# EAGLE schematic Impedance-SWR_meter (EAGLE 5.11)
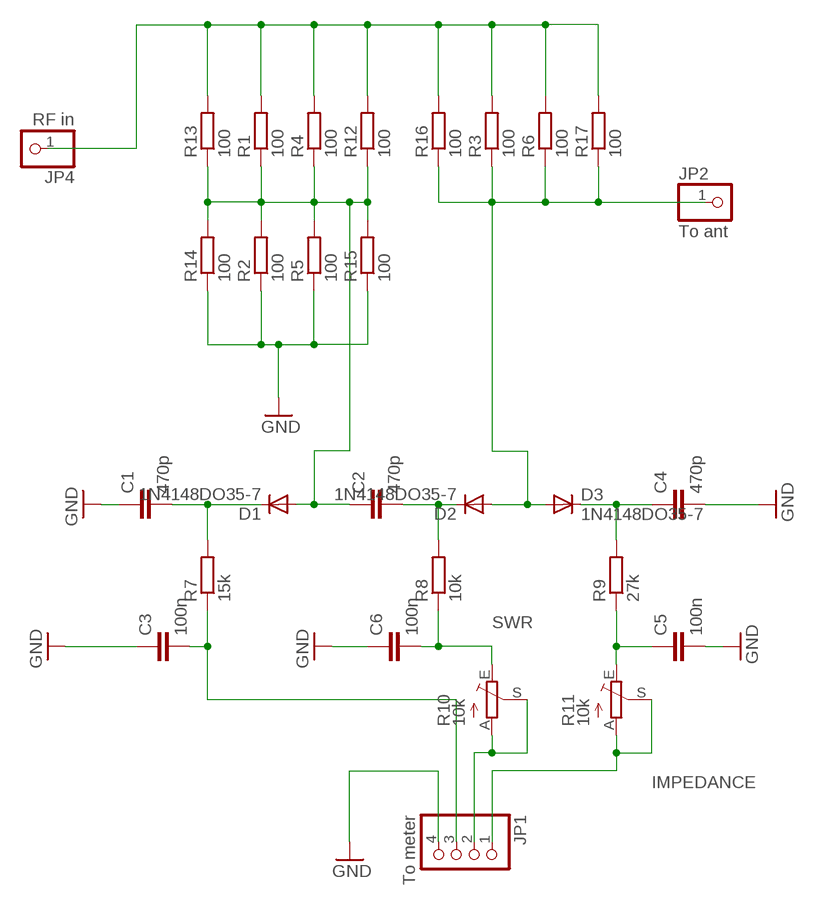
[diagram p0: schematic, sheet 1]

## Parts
C1  470p  C-EU025-060X050  [C025-060X050]
C2  470p  C-EU025-060X050  [C025-060X050]
C3  100n  C-EU025-060X050  [C025-060X050]
C4  470p  C-EU025-060X050  [C025-060X050]
C5  100n  C-EU025-060X050  [C025-060X050]
C6  100n  C-EU025-060X050  [C025-060X050]
D1  1N4148DO35-7  [DO35-7]
D2  1N4148DO35-7  [DO35-7]
D3  1N4148DO35-7  [DO35-7]
JP1  To meter  PINHD-1X4/90  [1X04/90]
JP2  To ant  PINHD-1X1  [1X01]
JP4  RF in  PINHD-1X1  [1X01]
R1  100  R-EU_M0805  [M0805]
R2  100  R-EU_M0805  [M0805]
R3  100  R-EU_M0805  [M0805]
R4  100  R-EU_M0805  [M0805]
R5  100  R-EU_M0805  [M0805]
R6  100  R-EU_M0805  [M0805]
R7  15k  R-EU_0309/12  [0309/12]
R8  10k  R-EU_0309/12  [0309/12]
R9  27k  R-EU_0309/12  [0309/12]
R10  10k  TRIM_EU-LI10  [LI10]
R11  10k  TRIM_EU-LI10  [LI10]
R12  100  R-EU_M0805  [M0805]
R13  100  R-EU_M0805  [M0805]
R14  100  R-EU_M0805  [M0805]
R15  100  R-EU_M0805  [M0805]
R16  100  R-EU_M0805  [M0805]
R17  100  R-EU_M0805  [M0805]

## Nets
GND: C1.1 C3.1 C4.2 C5.2 C6.1 JP1.4 R2.1 R5.1 R14.1 R15.1
IMPEDANCE: JP1.1 R11.A R11.S
N$1: C2.1 D1.A R1.1 R2.2 R4.1 R5.2 R12.1 R13.1 R14.2 R15.2
N$2: JP4.1 R1.2 R3.2 R4.2 R6.2 R12.2 R13.2 R16.2 R17.2
N$3: C1.2 D1.C R7.2
N$4: D2.A D3.A JP2.1 R3.1 R6.1 R16.1 R17.1
N$5: C3.2 JP1.3 R7.1
N$6: JP1.2 R10.A R10.S
N$7: C2.2 D2.C R8.2
N$10: C4.1 D3.C R9.2
N$15: C5.1 R9.1 R11.E
SWR: C6.2 R8.1 R10.E

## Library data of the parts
C1-C6 = rcl:C-EU: CAPACITOR, European symbol
D1-D3 = diode:1N4148: DIODE
JP1 = pinhead:PINHD-1X4: PIN HEADER
JP2 JP4 = pinhead:PINHD-1X1: PIN HEADER
R1-R9 R12-R17 = rcl:R-EU_: RESISTOR, European symbol
R10 R11 = pot:TRIM_EU-: POTENTIOMETER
